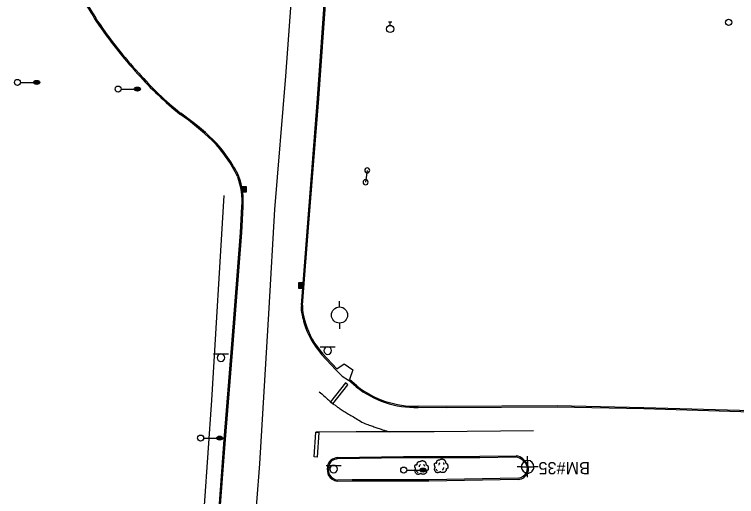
# Model space of a CAD drawing. Extents: x 2145380 to 2156929, y 139568 to 149130.
# Drawn here: x 2150937.5 to 2151294.3, y 140966.6 to 141204.9 of the extents above; entities that cross this region are included whole.
import ezdxf

# ---------------------------------------------------------------- set-up
doc = ezdxf.new("R2010")
doc.units = 0
for name, color, linetype in [('Default', 7, 'Continuous'), ('SURV_Benchmark', 7, 'Continuous'), ('SURV_Text', 7, 'Continuous'), ('TOPO_Asphalt', 7, 'Continuous'), ('TOPO_Curb Back', 7, 'Continuous'), ('TOPO_Fence', 7, 'Continuous'), ('TOPO_Light Pole', 7, 'Continuous'), ('TOPO_Misc', 7, 'Continuous'), ('TOPO_Misc Line', 7, 'Continuous'), ('TOPO_Power Pole', 7, 'Continuous'), ('TOPO_Sidewalk', 7, 'Continuous'), ('TOPO_Sign', 7, 'Continuous'), ('TOPO_Tree', 7, 'Continuous'), ('TOPO_Water Meter', 7, 'Continuous'), ('TOPO_Water Valve', 7, 'Continuous')]:
    doc.layers.add(name, color=color, linetype=linetype)

# ---------------------------------------------------------------- blocks, each defined once
blk = doc.blocks.new('LP')
at = {"layer": 'TOPO_Light Pole'}
blk.add_line((3.81, 0), (20.32, 0), dxfattribs=at)
for points in [[(20.32, 0), (27.94, 0)], [(20.32, 0), (23.5, 0)], [(20.83, 1.27), (27.43, 1.27)], [(20.83, 1.27), (23.5, 1.27)], [(23.71, 1.27), (27.43, 1.27)], [(23.71, 0), (27.94, 0)], [(20.83, -1.27), (27.43, -1.27)], [(20.83, -1.27), (23.5, -1.27)], [(23.71, -1.27), (27.43, -1.27)]]:
    blk.add_lwpolyline(points, dxfattribs=at)
blk.add_circle((0, 0), 3.81, dxfattribs=at)
blk.add_ellipse((24.13, 0), major_axis=(3.81, 0), ratio=0.666667, dxfattribs=at)
blk = doc.blocks.new('POST')
at = {"layer": 'TOPO_Misc'}
for start, end in [(89.99996, 180.00004), (179.99996, 270.00004), (359.99996, 90.00004), (269.99996, 0.00004)]:
    blk.add_arc((-0.01, 0.03), 3.16, start, end, dxfattribs=at)
blk = doc.blocks.new('CB')
at = {"layer": 'TOPO_Misc'}
for p, q in [((-3.08, 2.99), (3.24, 2.99)), ((-3.08, 2.68), (3.24, 2.68)), ((-3.08, 2.36), (3.24, 2.36)), ((-3.08, 2.05), (3.24, 2.05)), ((-3.08, 1.73), (3.24, 1.73)), ((-3.08, 1.4), (3.24, 1.4)), ((-3.08, 1.1), (3.24, 1.1)), ((-3.08, 0.77), (3.24, 0.77)), ((-3.08, 0.46), (3.24, 0.46)), ((-3.08, 0.14), (3.24, 0.14)), ((-3.08, -0.17), (3.24, -0.17)), ((-3.08, -0.48), (3.24, -0.48)), ((-3.08, -0.8), (3.24, -0.8)), ((-3.08, -1.11), (3.26, -1.11)), ((-3.08, -1.43), (3.26, -1.43)), ((-3.08, -1.75), (3.26, -1.75)), ((-3.08, -2.07), (3.26, -2.07)), ((-3.08, -2.39), (3.26, -2.39)), ((-3.08, -2.7), (3.26, -2.7)), ((-3.08, -3.02), (3.26, -3.02))]:
    blk.add_line(p, q, dxfattribs=at)
blk.add_lwpolyline([(3.26, -3.29), (3.24, 3.05), (-3.09, 3.04), (-3.08, -3.3), (3.26, -3.29)], dxfattribs=at)
blk = doc.blocks.new('TREE')
at = {"layer": 'TOPO_Tree'}
for points in [[(-14.1, -0.4), (-14.2, 0.5), (-14.4, 1.4), (-14.6, 2.3), (-14.8, 3.2), (-15.5, 4), (-15.7, 4.9), (-15.8, 5.6), (-15.7, 6.3), (-15.7, 7), (-15.6, 7.9), (-15.7, 8.8), (-15.1, 9.7), (-14.6, 10.4), (-13.8, 10.5), (-13, 10.7), (-12.2, 11), (-11.1, 10), (-10.4, 10.7), (-9.4, 11.7), (-10.3, 13.3), (-9.8, 14.4), (-9.6, 15.1), (-9.3, 15.9), (-8.8, 16.5), (-8.2, 17.3), (-7.5, 17.7), (-6.7, 18.1), (-6.1, 18.4), (-5.6, 18.6), (-5.1, 18.7), (-4.5, 18.7), (-4, 18.5), (-3.5, 18.1)], [(-3.5, 17.6), (-3.1, 18.3), (-2.6, 18.8), (-1.9, 19.2), (-1, 19.7), (-0.2, 20), (0.7, 20.2), (1.6, 20.5), (2.5, 20.8), (3.4, 20.8), (4.1, 20.7), (4.8, 20.5), (5.5, 20.2), (6.4, 19.9), (7.3, 19.7), (8.2, 19.2), (9.4, 18.4), (10, 17.2), (10.8, 16), (11.2, 15.3), (11.6, 14.6), (11.9, 13.9), (12.2, 13.1), (11.4, 12), (11.9, 11.2), (12, 11), (12.2, 10.9), (12.4, 10.7), (12.9, 10.4), (13.5, 10), (14, 9.7), (14.7, 9.2), (15.4, 8.7), (16.1, 8.1), (16.7, 7.5), (16.9, 6.7), (17.1, 6), (17.6, 4.4), (17.7, 2.8), (17.7, 1.2), (17.7, -0.2), (17.8, -2.2), (16.6, -3), (15.5, -3.8), (14.3, -4.6), (13.2, -5.3)], [(13.2, -5.3), (13.3, -5.8), (13.4, -6.3), (13.4, -6.7), (13.8, -8.5), (12.2, -10), (10.8, -11.5), (10, -12.3), (9.1, -12.8), (8.2, -13.1), (6, -13.8), (3.3, -13.6), (1.3, -13.1), (0.5, -12.9), (-0.1, -11.4), (-0.8, -11.5), (-2, -11.6), (-3.3, -12.8), (-4.5, -13.1), (-6.1, -13.5), (-7.8, -14), (-9.3, -13.6), (-11.4, -13.1), (-12.8, -11.4), (-14.1, -9.4), (-15.3, -7.3), (-15.6, -5.1), (-15.1, -3), (-14.9, -1.9), (-13.9, -0.8), (-13.5, 0.1)], [(-4.2, 5.1), (-4.5, 6.1), (-4.3, 7.2), (-3.8, 8.2), (-3.3, 9.3), (-2.7, 10.3), (-1.6, 11)], [(5.9, 11.2), (6.5, 10.7), (7, 10.2), (7.4, 9.5), (7.9, 8.6), (8.3, 7.6), (8.5, 6.6)], [(-11.4, -4.5), (-11.5, -5.4), (-11, -6.3), (-10.1, -7.2), (-9.3, -8), (-8.5, -8.3), (-7.7, -8.1)], [(4.8, -6.3), (5.7, -5.7), (6.3, -4.9), (6.8, -3.9), (7.4, -2.8), (7.6, -1.7), (7.5, -0.6)]]:
    blk.add_open_spline(points, degree=3, dxfattribs=at)
blk = doc.blocks.new('POWPOL')
at = {"layer": 'TOPO_Power Pole'}
for p, q in [((0, 10.16), (0, 17.34)), ((0, -10.16), (0, -17.34))]:
    blk.add_line(p, q, dxfattribs=at)
blk.add_circle((0, 0), 10.16, dxfattribs=at)
blk = doc.blocks.new('WATVAL')
at = {"layer": 'Default'}
for p, q in [((-2.25, 9), (2.25, 9)), ((0, 4.5), (0, 9))]:
    blk.add_line(p, q, dxfattribs=at)
blk.add_circle((0, 0), 4.5, dxfattribs=at)
blk = doc.blocks.new('WTRMTR')
at = {"layer": 'Default'}
blk.add_circle((0, 0), 3.89, dxfattribs=at)
blk = doc.blocks.new('BM')
at = {"layer": 'SURV_Benchmark'}
for p, q in [((0, 2.49), (0, 4.15)), ((-2.49, 0), (-4.16, 0)), ((4.16, 0), (2.49, 0)), ((0, -4.16), (0, -2.49))]:
    blk.add_line(p, q, dxfattribs=at)
for points in [[(-2.5, 0), (-2.49, 0), (0, 0), (0, -2.49), (0, -2.49)], [(-2.5, 0), (-2.49, 0), (0, 0), (0, -2.49), (0, -2.49)], [(0, 2.49), (0, 2.49), (0, 0), (2.49, 0), (2.49, 0), (2.49, 0)], [(0, 2.49), (0, 2.49), (0, 0), (2.49, 0), (2.49, 0), (2.49, 0), (2.49, 0)]]:
    blk.add_lwpolyline(points, dxfattribs=at)
for start, end in [(90.0638, 180.0068), (0.0638, 90.0068), (0.0638, 90.0068), (180.0638, 270.0068), (180.0638, 270.0068), (269.9472, 359.9927)]:
    blk.add_arc((0, 0), 2.5, start, end, dxfattribs=at)

msp = doc.modelspace()

# ---------------------------------------------------------------- linework, layer by layer
at = {"layer": 'TOPO_Asphalt'}
msp.add_lwpolyline([(2151096.32, 141029.23), (2151099.51, 141026.09), (2151102.6, 141024.05)], dxfattribs=at)
at = {"layer": 'TOPO_Curb Back'}
for points in [[(2151079.3, 141061.22), (2151082.44, 141101.79), (2151087.25, 141163.36), (2151091.05, 141216.85), (2151092.2, 141229.01)], [(2151079.9, 141061.16), (2151083.04, 141101.74), (2151087.85, 141163.32), (2151091.65, 141216.8), (2151092.8, 141228.97)], [(2151025.02, 140780.67), (2151028.21, 140824.99), (2151030.65, 140858.37), (2151034.32, 140904.11), (2151037.96, 140951.8), (2151041.14, 140994.73), (2151045.01, 141041.94), (2151049.22, 141097.05), (2151049.87, 141109.87)], [(2151025.62, 140780.63), (2151028.81, 140824.95), (2151031.25, 140858.32), (2151034.92, 140904.06), (2151038.56, 140951.76), (2151041.74, 140994.69), (2151045.61, 141041.89), (2151049.82, 141097.01), (2151050.47, 141109.83)], [(2151096.32, 141029.23), (2151089.32, 141036.84)], [(2151096.76, 141029.64), (2151089.76, 141037.24)], [(2151106.32, 141020.81), (2151102.6, 141024.05)], [(2151106.7, 141021.27), (2151103, 141024.5)], [(2151436.59, 141007.48), (2151405.76, 141007.41), (2151353.01, 141007.38), (2151301.79, 141008.86), (2151248.45, 141010.47), (2151205.74, 141011.42), (2151150.84, 141011.07), (2151136.93, 141011.24)], [(2151436.58, 141006.88), (2151405.76, 141006.81), (2151353, 141006.78), (2151301.78, 141008.26), (2151248.44, 141009.87), (2151205.73, 141010.82), (2151150.84, 141010.47), (2151136.93, 141010.64)], [(2151097.17, 140985.9), (2151129.83, 140986.43), (2151167.45, 140986.5), (2151185.51, 140986.76)], [(2151097.23, 140985.3), (2151129.84, 140985.83), (2151167.46, 140985.9), (2151185.45, 140986.16)], [(2151186.49, 140975.01), (2151142.23, 140974.16), (2151104.38, 140974.18), (2151097.02, 140974.09)], [(2151186.48, 140975.61), (2151142.23, 140974.76), (2151104.38, 140974.78), (2151097.07, 140974.69)]]:
    msp.add_lwpolyline(points, dxfattribs=at)
for centre, radius, start, end in [((2151322.35, 141419.46), 407.58, 208.2545, 212.3787), ((2151322.38, 141419.48), 407.01, 208.2579, 212.3772), ((2151165.12, 141328), 225.92, 214.1421, 222.4991), ((2151165.11, 141327.99), 225.31, 214.1443, 222.5009), ((2151122.4, 141284.59), 165.12, 221.4076, 231.3605), ((2151122.41, 141284.59), 164.54, 221.4058, 231.3543), ((2150927.69, 141027.36), 157.6, 46.9416, 54.4643), ((2150927.68, 141027.34), 158.23, 46.938, 54.4581), ((2150988.55, 141096.42), 65.65, 25.3324, 44.6004), ((2150988.56, 141096.42), 66.24, 25.3075, 44.611), ((2151014.87, 141112.58), 35.11, 355.5707, 19.8626), ((2151014.87, 141112.58), 35.71, 355.583, 19.9089), ((2151093.87, 141059.67), 14.65, 173.9291, 193.3086), ((2151093.87, 141059.67), 14.05, 173.8946, 193.298), ((2151211.59, 141088.6), 135.87, 193.7527, 195.5498), ((2151211.35, 141088.54), 135.03, 193.7529, 195.5496), ((2151119.21, 141063.76), 40.22, 196.7323, 222.0058), ((2151119.21, 141063.76), 39.62, 196.7413, 222.0011), ((2151135.64, 141057.93), 47.3, 231.6911, 271.5635), ((2151135.64, 141057.93), 46.7, 231.709, 271.578), ((2151097.56, 140980.72), 5.36, 133.1167, 174.3522), ((2151098.64, 140977.28), 8.74, 99.655, 122.8596), ((2151098.64, 140977.28), 8.14, 99.9724, 122.4748), ((2151183.48, 140978.27), 8.13, 28.9945, 76.0043), ((2151183.48, 140978.27), 8.73, 28.7852, 76.5263), ((2151099.41, 140979.9), 7.31, 169.3732, 203.9447), ((2151099.41, 140979.9), 6.71, 169.1494, 203.5024), ((2151097.56, 140980.72), 4.76, 133.7575, 174.6648), ((2151186.31, 140980.4), 4.65, 338.499, 22.8398), ((2151186.31, 140980.4), 5.25, 338.4428, 23.1983), ((2151098.26, 140980.63), 6.05, 214.2386, 258.6852), ((2151185.97, 140980.63), 5.05, 275.4932, 337.5457), ((2151185.97, 140980.63), 5.65, 275.4932, 337.5957), ((2151098.26, 140980.63), 6.65, 213.7522, 259.2388)]:
    msp.add_arc(centre, radius, start, end, dxfattribs=at)
at = {"layer": 'TOPO_Fence'}
msp.add_lwpolyline([(2151041.02, 141115.38), (2151034.92, 141014.26), (2151027.66, 140910.05), (2151020.5, 140804.14), (2151018.36, 140771.93)], dxfattribs=at)
at = {"layer": 'TOPO_Misc Line'}
for points in [[(2151041.75, 140781.11), (2151049.08, 140860.42), (2151052.85, 140906.23), (2151058.7, 140982.78), (2151063.39, 141059.75), (2151066.17, 141108.4), (2151071.65, 141174.32), (2151075.3, 141224.03), (2151077.64, 141296.7), (2151070.94, 141376.27), (2151055.2, 141462.47), (2151041.34, 141511.84)], [(2151193.99, 140999.02), (2151144.92, 140998.6), (2151106.35, 140998.54), (2151086.42, 140998.32)]]:
    msp.add_lwpolyline(points, dxfattribs=at)
for points in [[(2151101.07, 141022.72), (2151093.65, 141013.45), (2151094.91, 141012.44), (2151102.33, 141021.72)], [(2151085.59, 140986.14), (2151086.42, 140998.32), (2151087.91, 140998.22), (2151087.09, 140986.03)]]:
    msp.add_lwpolyline(points, close=True, dxfattribs=at)
msp.add_open_spline([(2151088.11, 141018.4), (2151089.96, 141016.75), (2151091.8, 141015.1), (2151093.65, 141013.45), (2151095.06, 141012.39), (2151096.46, 141011.33), (2151097.87, 141010.27), (2151099.99, 141008.98), (2151102.12, 141007.69), (2151104.24, 141006.4), (2151107.05, 141004.69), (2151109.9, 141002.93), (2151113.01, 141001.84), (2151115.08, 141001.1), (2151117.16, 141000.37), (2151119.24, 140999.64), (2151120.4, 140999.28), (2151121.55, 140998.92), (2151122.71, 140998.57)], degree=3, dxfattribs=at)
at = {"layer": 'TOPO_Sidewalk'}
msp.add_lwpolyline([(2151096.76, 141029.67), (2151100.4, 141032.09), (2151104.68, 141029.2), (2151103, 141024.5)], dxfattribs=at)
at = {"layer": 'TOPO_Sign'}
for points in [[(2151111.83, 141127.78), (2151111.02, 141121.9)], [(2151088.55, 141040.55), (2151096.04, 141040.56)], [(2151090.43, 141038.68), (2151090.43, 141038.68)], [(2151092.3, 141040.55), (2151092.3, 141040.55)], [(2151094.16, 141038.68), (2151094.16, 141038.68)], [(2151035.83, 141037.07), (2151043.32, 141037.07)], [(2151037.71, 141035.2), (2151037.71, 141035.2)], [(2151039.58, 141037.07), (2151039.58, 141037.07)], [(2151041.45, 141035.2), (2151041.45, 141035.2)], [(2151092.3, 141036.81), (2151092.3, 141036.81)], [(2151039.58, 141033.33), (2151039.58, 141033.33)], [(2151091.5, 140981.99), (2151098.99, 140981.99)], [(2151095.25, 140981.99), (2151095.25, 140981.99)], [(2151093.38, 140980.12), (2151093.38, 140980.12)], [(2151095.25, 140978.25), (2151095.25, 140978.25)], [(2151097.12, 140980.12), (2151097.12, 140980.12)]]:
    msp.add_lwpolyline(points, dxfattribs=at)
for centre, start, end in [((2151092.3, 141038.68), 90, 180), ((2151092.3, 141038.68), 180, 270), ((2151092.3, 141038.68), 360, 90), ((2151092.3, 141038.68), 270, 0), ((2151039.58, 141035.2), 90, 180), ((2151039.58, 141035.2), 180, 270), ((2151039.58, 141035.2), 360, 90), ((2151039.58, 141035.2), 270, 0), ((2151095.25, 140980.12), 90, 180), ((2151095.25, 140980.12), 360, 90), ((2151095.25, 140980.12), 180, 270), ((2151095.25, 140980.12), 270, 0)]:
    msp.add_arc(centre, 1.87, start, end, dxfattribs=at)

# ---------------------------------------------------------------- block references
at = {"layer": 'SURV_Benchmark', "xscale": 1.2499999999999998, "yscale": 1.25}
msp.add_blockref('BM', (2151191.09, 140981.27), dxfattribs=at)
at = {"layer": 'TOPO_Light Pole', "xscale": 0.39370000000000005, "yscale": 0.3937000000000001}
for p in [(2150939.02, 141171.28), (2150988.76, 141167.97), (2151029.48, 140995.45), (2151129.9, 140979.65)]:
    msp.add_blockref('LP', p, dxfattribs=at)
at = {"layer": 'TOPO_Misc', "xscale": 0.39370000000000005, "yscale": 0.3937000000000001}
for name, p in [('POST', (2151111.83, 141127.78)), ('POST', (2151111.02, 141121.9)), ('CB', (2151050.92, 141118.47)), ('CB', (2151079.17, 141070.94))]:
    msp.add_blockref(name, p, dxfattribs=at)
at = {"layer": 'TOPO_Power Pole', "xscale": 0.39370000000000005, "yscale": 0.3937000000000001}
msp.add_blockref('POWPOL', (2151098.15, 141056.27), dxfattribs=at)
at = {"layer": 'TOPO_Tree', "xscale": 0.19685000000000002, "yscale": 0.19685000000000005}
for p in [(2151138.5, 140980.24), (2151148.16, 140981.07)]:
    msp.add_blockref('TREE', p, dxfattribs=at)
at = {"layer": 'TOPO_Water Meter', "xscale": 0.39370000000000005, "yscale": 0.3937000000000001}
msp.add_blockref('WTRMTR', (2151290.41, 141200.99), dxfattribs=at)
at = {"layer": 'TOPO_Water Valve', "xscale": 0.39370000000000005, "yscale": 0.3937000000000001}
msp.add_blockref('WATVAL', (2151123.17, 141197.68), dxfattribs=at)

# ---------------------------------------------------------------- texts
at = {"layer": 'SURV_Text'}
msp.add_text('BM#35', height=6, rotation=180, dxfattribs=at).set_placement((2151221.87, 140983.6))

doc.saveas('drawing.dxf')
